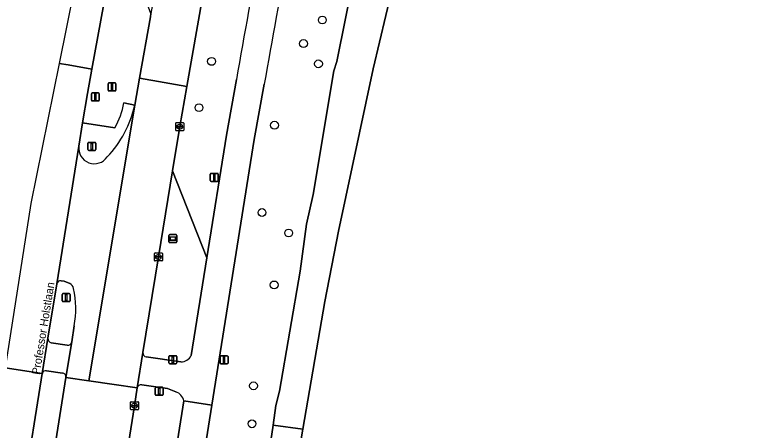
# Model space of a CAD drawing. Extents: x 160203 to 161530, y 379528 to 381797.
# Drawn here: x 160355.6 to 160448.4, y 380603.3 to 380655.1 of the extents above; entities that cross this region are included whole.
import ezdxf

# ---------------------------------------------------------------- set-up
doc = ezdxf.new("R2010")
doc.units = 0
for name, color, linetype in [('IMGEO_Berm_groen', 7, 'Continuous'), ('IMGEO_Boom', 7, 'Continuous'), ('IMGEO_Drukknoppaal', 7, 'Continuous'), ('IMGEO_Fietspad_gesloten', 7, 'Continuous'), ('IMGEO_Fietspad_open', 7, 'Continuous'), ('IMGEO_Grasland_agrarisch', 7, 'Continuous'), ('IMGEO_Kolk', 7, 'Continuous'), ('IMGEO_Lichtmast', 7, 'Continuous'), ('IMGEO_Oever', 7, 'Continuous'), ('IMGEO_Openbare_ruimte_label', 7, 'Continuous'), ('IMGEO_Rijbaan_regionaal_gesloten', 7, 'Continuous'), ('IMGEO_Verkeersbordpaal', 7, 'Continuous'), ('IMGEO_Verkeerseiland_open', 7, 'Continuous'), ('IMGEO_Waterloop', 7, 'Continuous'), ('IMGEO_Wegwijzer', 7, 'Continuous')]:
    doc.layers.add(name, color=color, linetype=linetype)

msp = doc.modelspace()

# ---------------------------------------------------------------- linework, layer by layer
at = {"layer": 'IMGEO_Berm_groen'}
for points in [[(160400.668, 380735.378), (160401.67, 380738.517), (160393.665, 380729.151), (160393.718, 380725.652), (160393.414, 380724.394), (160392.616, 380724.543), (160388.081, 380703.507), (160383.995, 380683.446), (160379.783, 380661.35), (160377.1, 380646.154), (160376.217, 380641.153), (160375.315, 380635.633), (160379.602, 380624.787), (160382.053, 380640.078), (160383.286, 380647.043)], [(160386.211, 380592.747), (160387.862, 380603.942), (160388.223, 380606.389), (160388.675, 380608.166), (160391.266, 380623.144), (160392.046, 380629.012), (160392.89, 380632.678), (160395.463, 380648.127), (160395.831, 380649.266), (160397.982, 380660.047), (160413.118, 380722.694), (160414.318, 380728.603)], [(160372.548, 380654.869), (160372.618, 380655.25), (160368.532, 380666.24), (160365.264, 380648.34), (160364.706, 380645.285), (160364.09, 380641.636), (160368.101, 380641.026)], [(160369.244, 380644.107), (160370.61, 380643.846), (160371.203, 380647.217), (160372.548, 380654.869)], [(160386.76, 380646.455), (160385.522, 380639.561), (160380.205, 380606.406), (160371.189, 380549.526)], [(160379.602, 380624.787), (160375.315, 380635.633), (160373.561, 380624.901), (160371.602, 380612.968)], [(160377.651, 380612.613), (160379.602, 380624.787)], [(160372.039, 380612.43), (160376.36, 380611.804)], [(160359.064, 380610.365), (160356.772, 380595.979), (160358.163, 380585.647), (160362.001, 380609.884)], [(160361.581, 380610.416), (160359.604, 380610.72)], [(160370.92, 380608.573), (160370.572, 380606.348), (160367.595, 380587.549), (160367.388, 380586.261), (160374.855, 380595.163), (160376.723, 380606.946)], [(160375.736, 380608.096), (160374.693, 380608.486), (160371.472, 380608.969)]]:
    msp.add_lwpolyline(points, dxfattribs=at)
for centre, radius, start, end in [((161737.825, 380406.88), 1375.665, 168.507493, 169.945799), ((162016.34, 380355.518), 1655.347, 168.699277, 169.877338), ((160361.073, 380645.386), 8.271, 328.18726, 351.1047), ((160372.143, 380612.961), 0.541, 179.27552, 258.89616), ((160376.321, 380613.301), 1.497, 271.49548, 332.65082), ((160359.517, 380610.264), 0.464, 79.16832, 167.47411), ((160361.54, 380609.952), 0.466, 351.66885, 84.91148), ((160371.397, 380608.49), 0.484, 81.13593, 170.17472), ((160375.175, 380606.616), 1.582, 12.026, 69.2504)]:
    msp.add_arc(centre, radius, start, end, dxfattribs=at)
at = {"layer": 'IMGEO_Boom'}
for centre in [(160394.025, 380654.451), (160391.671, 380651.517), (160380.192, 380649.292), (160393.535, 380648.988), (160378.626, 380643.518), (160388.05, 380641.33), (160386.493, 380630.443), (160389.817, 380627.893), (160388.006, 380621.413), (160385.426, 380608.831), (160385.234, 380604.095)]:
    msp.add_circle(centre, 0.489, dxfattribs=at)
at = {"layer": 'IMGEO_Drukknoppaal'}
for p, q in [((160365.182, 380644.461), (160365.182, 380645.261)), ((160365.182, 380645.261), (160365.182, 380644.461)), ((160365.282, 380645.361), (160366.072, 380645.361)), ((160366.072, 380645.361), (160365.282, 380645.361)), ((160366.172, 380645.261), (160366.172, 380644.461)), ((160366.172, 380644.461), (160366.172, 380645.261)), ((160366.072, 380644.361), (160365.282, 380644.361)), ((160365.282, 380644.361), (160366.072, 380644.361)), ((160364.857, 380639.19), (160365.647, 380639.19)), ((160365.647, 380639.19), (160364.857, 380639.19)), ((160364.757, 380638.29), (160364.757, 380639.09)), ((160364.757, 380639.09), (160364.757, 380638.29)), ((160365.647, 380638.19), (160364.857, 380638.19)), ((160364.857, 380638.19), (160365.647, 380638.19)), ((160365.747, 380639.09), (160365.747, 380638.29)), ((160365.747, 380638.29), (160365.747, 380639.09)), ((160374.861, 380611.685), (160374.861, 380612.485)), ((160374.861, 380612.485), (160374.861, 380611.685)), ((160374.961, 380612.585), (160375.751, 380612.585)), ((160375.751, 380612.585), (160374.961, 380612.585)), ((160375.851, 380612.485), (160375.851, 380611.685)), ((160375.851, 380611.685), (160375.851, 380612.485)), ((160375.751, 380611.585), (160374.961, 380611.585)), ((160374.961, 380611.585), (160375.751, 380611.585))]:
    msp.add_line(p, q, dxfattribs=at)
for points in [[(160365.602, 380645.236), (160365.752, 380645.236), (160365.752, 380644.486), (160365.602, 380644.486), (160365.602, 380645.236)], [(160365.177, 380639.065), (160365.327, 380639.065), (160365.327, 380638.315), (160365.177, 380638.315), (160365.177, 380639.065)], [(160375.281, 380612.46), (160375.431, 380612.46), (160375.431, 380611.71), (160375.281, 380611.71), (160375.281, 380612.46)]]:
    msp.add_lwpolyline(points, dxfattribs=at)
for centre, start, end in [((160365.282, 380645.261), 90, 180), ((160365.282, 380645.261), 90, 180), ((160366.072, 380645.261), 0, 90), ((160366.072, 380645.261), 360, 90), ((160365.282, 380644.461), 180, 270), ((160365.282, 380644.461), 180, 270), ((160366.072, 380644.461), 270, 0), ((160366.072, 380644.461), 270, 0), ((160364.857, 380639.09), 90, 180), ((160364.857, 380639.09), 90, 180), ((160365.647, 380639.09), 0, 90), ((160365.647, 380639.09), 360, 90), ((160364.857, 380638.29), 180, 270), ((160364.857, 380638.29), 180, 270), ((160365.647, 380638.29), 270, 0), ((160365.647, 380638.29), 270, 0), ((160374.961, 380612.485), 90, 180), ((160374.961, 380612.485), 90, 180), ((160375.751, 380612.485), 0, 90), ((160375.751, 380612.485), 360, 90), ((160374.961, 380611.685), 180, 270), ((160374.961, 380611.685), 180, 270), ((160375.751, 380611.685), 270, 0), ((160375.751, 380611.685), 270, 0)]:
    msp.add_arc(centre, 0.1, start, end, dxfattribs=at)
at = {"layer": 'IMGEO_Fietspad_gesloten'}
for points in [[(160383.286, 380647.043), (160382.053, 380640.078), (160379.602, 380624.787), (160377.651, 380612.613)], [(160376.723, 380606.946), (160380.205, 380606.406), (160385.522, 380639.561), (160386.76, 380646.455)], [(160371.602, 380612.968), (160370.92, 380608.573)], [(160376.36, 380611.804), (160372.039, 380612.43)], [(160371.472, 380608.969), (160374.693, 380608.486), (160375.736, 380608.096)]]:
    msp.add_lwpolyline(points, dxfattribs=at)
msp.add_lwpolyline([(160380.205, 380606.406), (160376.723, 380606.946), (160374.855, 380595.163), (160367.706, 380550.056), (160363.967, 380526.659), (160359.706, 380500), (160358.293, 380491.158), (160351.85, 380450.983), (160355.339, 380450.611), (160361.784, 380490.887), (160363.246, 380500), (160367.433, 380526.109), (160371.189, 380549.526)], close=True, dxfattribs=at)
for centre, radius, start, end in [((161737.825, 380406.88), 1375.665, 168.507493, 169.945799), ((162016.34, 380355.518), 1655.347, 168.699277, 169.877338), ((160372.143, 380612.961), 0.541, 179.27552, 258.89616), ((160376.321, 380613.301), 1.497, 271.49548, 332.65082), ((160371.397, 380608.49), 0.484, 81.13593, 170.17472), ((160375.175, 380606.616), 1.582, 12.026, 69.2504)]:
    msp.add_arc(centre, radius, start, end, dxfattribs=at)
at = {"layer": 'IMGEO_Fietspad_open'}
for points in [[(160359.767, 380614.757), (160359.064, 380610.365)], [(160362.159, 380613.9), (160360.16, 380614.208)], [(160362.001, 380609.884), (160362.736, 380614.304)], [(160359.604, 380610.72), (160361.581, 380610.416)]]:
    msp.add_lwpolyline(points, dxfattribs=at)
for centre, radius, start, end in [((160360.28, 380614.709), 0.515, 174.62319, 256.57055), ((160362.219, 380614.429), 0.532, 263.57434, 346.42303), ((160359.517, 380610.264), 0.464, 79.16832, 167.47411), ((160361.54, 380609.952), 0.466, 351.66885, 84.91148)]:
    msp.add_arc(centre, radius, start, end, dxfattribs=at)
at = {"layer": 'IMGEO_Grasland_agrarisch'}
msp.add_lwpolyline([(160502.576, 380648.6), (160500, 380662.54), (160490.099, 380716.119), (160490.004, 380717.605), (160489.849, 380720.043), (160487.28, 380732.369), (160483.606, 380750), (160481.082, 380763.132), (160480.966, 380763.072), (160477.636, 380759.084), (160472.153, 380755.572), (160467.543, 380753.714), (160457.317, 380750.88), (160446.558, 380749.443), (160436.701, 380749.566), (160431.609, 380749.895), (160424.751, 380748.622), (160421.704, 380738.223), (160400.367, 380648.355), (160396.021, 380628.131), (160394.312, 380619.353), (160391.591, 380603.409), (160387.523, 380579.574)], dxfattribs=at)
at = {"layer": 'IMGEO_Kolk'}
for p, q in [((160375.717, 380640.726), (160375.717, 380641.578)), ((160375.792, 380641.652), (160376.644, 380641.652)), ((160375.976, 380641.146), (160375.976, 380641.158)), ((160376.414, 380641.109), (160376.016, 380641.109)), ((160376.019, 380641.195), (160376.417, 380641.195)), ((160376.205, 380641.432), (160376.23, 380641.432)), ((160376.46, 380641.158), (160376.46, 380641.146)), ((160376.718, 380641.578), (160376.718, 380640.726)), ((160376.644, 380640.652), (160375.792, 380640.652)), ((160376.228, 380640.872), (160376.203, 380640.872)), ((160373.059, 380624.476), (160373.059, 380625.328)), ((160373.134, 380625.402), (160373.986, 380625.402)), ((160373.547, 380625.182), (160373.572, 380625.182)), ((160374.06, 380625.328), (160374.06, 380624.476)), ((160373.986, 380624.402), (160373.134, 380624.402)), ((160373.318, 380624.896), (160373.318, 380624.908)), ((160373.756, 380624.859), (160373.358, 380624.859)), ((160373.361, 380624.945), (160373.759, 380624.945)), ((160373.57, 380624.622), (160373.545, 380624.622)), ((160373.802, 380624.908), (160373.802, 380624.896)), ((160370.072, 380605.922), (160370.072, 380606.774)), ((160370.147, 380606.848), (160370.999, 380606.848)), ((160370.56, 380606.628), (160370.585, 380606.628)), ((160371.073, 380606.774), (160371.073, 380605.922)), ((160370.999, 380605.848), (160370.147, 380605.848)), ((160370.331, 380606.342), (160370.331, 380606.354)), ((160370.769, 380606.305), (160370.371, 380606.305)), ((160370.374, 380606.391), (160370.772, 380606.391)), ((160370.583, 380606.068), (160370.558, 380606.068)), ((160370.815, 380606.354), (160370.815, 380606.342))]:
    msp.add_line(p, q, dxfattribs=at)
for points in [[(160375.717, 380640.726), (160375.717, 380641.578)], [(160375.792, 380641.652), (160376.644, 380641.652)], [(160376.718, 380641.578), (160376.718, 380640.726)], [(160376.644, 380640.652), (160375.792, 380640.652)], [(160373.059, 380624.476), (160373.059, 380625.328)], [(160373.134, 380625.402), (160373.986, 380625.402)], [(160374.06, 380625.328), (160374.06, 380624.476)], [(160373.986, 380624.402), (160373.134, 380624.402)], [(160370.072, 380605.922), (160370.072, 380606.774)], [(160370.147, 380606.848), (160370.999, 380606.848)], [(160371.073, 380606.774), (160371.073, 380605.922)], [(160370.999, 380605.848), (160370.147, 380605.848)]]:
    msp.add_lwpolyline(points, dxfattribs=at)
for centre, radius, start, end in [((160375.794, 380641.576), 0.0765, 91.55205, 178.44795), ((160375.794, 380641.576), 0.0765, 91.55205, 178.44795), ((160376.016, 380641.155), 0.0403, 85.87752, 175.75265), ((160376.013, 380641.145), 0.0366, 178.93798, 274.71019), ((160376.417, 380641.152), 0.043, 264.86636, 352.45326), ((160376.421, 380641.157), 0.0386, 1.73085, 96.63898), ((160376.642, 380641.576), 0.0765, 1.55205, 88.44795), ((160376.642, 380641.576), 0.0765, 1.55205, 88.44795), ((160375.794, 380640.728), 0.0765, 181.55205, 268.44795), ((160375.794, 380640.728), 0.0765, 181.55205, 268.44795), ((160376.642, 380640.728), 0.0765, 271.55205, 358.44795), ((160376.642, 380640.728), 0.0765, 271.55205, 358.44795), ((160373.136, 380625.326), 0.0765, 91.55205, 178.44795), ((160373.136, 380625.326), 0.0765, 91.55205, 178.44795), ((160373.984, 380625.326), 0.0765, 1.55205, 88.44795), ((160373.984, 380625.326), 0.0765, 1.55205, 88.44795), ((160373.136, 380624.478), 0.0765, 181.55205, 268.44795), ((160373.136, 380624.478), 0.0765, 181.55205, 268.44795), ((160373.358, 380624.905), 0.0403, 85.87752, 175.75265), ((160373.355, 380624.895), 0.0366, 178.93798, 274.71019), ((160373.759, 380624.902), 0.043, 264.86636, 352.45326), ((160373.763, 380624.907), 0.0386, 1.73085, 96.63898), ((160373.984, 380624.478), 0.0765, 271.55205, 358.44795), ((160373.984, 380624.478), 0.0765, 271.55205, 358.44795), ((160370.149, 380606.772), 0.0765, 91.55205, 178.44795), ((160370.149, 380606.772), 0.0765, 91.55205, 178.44795), ((160370.997, 380606.772), 0.0765, 1.55205, 88.44795), ((160370.997, 380606.772), 0.0765, 1.55205, 88.44795), ((160370.149, 380605.924), 0.0765, 181.55205, 268.44795), ((160370.149, 380605.924), 0.0765, 181.55205, 268.44795), ((160370.371, 380606.351), 0.0403, 85.87752, 175.75265), ((160370.368, 380606.341), 0.0366, 178.93798, 274.71019), ((160370.772, 380606.348), 0.043, 264.86636, 352.45326), ((160370.776, 380606.353), 0.0386, 1.73085, 96.63898), ((160370.997, 380605.924), 0.0765, 271.55205, 358.44795), ((160370.997, 380605.924), 0.0765, 271.55205, 358.44795)]:
    msp.add_arc(centre, radius, start, end, dxfattribs=at)
for centre, major_axis, ratio, start_param, end_param in [((160376.204, 380641.152), (-0.387, 0.002), 0.722429, 4.712389, 7.853982), ((160376.229, 380641.152), (-0.39, 0.002), 0.717154, 1.570796, 4.712389), ((160373.546, 380624.902), (-0.387, 0.002), 0.722429, 4.712389, 7.853982), ((160373.571, 380624.902), (-0.39, 0.002), 0.717154, 1.570796, 4.712389), ((160370.559, 380606.348), (-0.387, 0.002), 0.722429, 4.712389, 7.853982), ((160370.584, 380606.348), (-0.39, 0.002), 0.717154, 1.570796, 4.712389)]:
    msp.add_ellipse(centre, major_axis=major_axis, ratio=ratio, start_param=start_param, end_param=end_param, dxfattribs=at)
at = {"layer": 'IMGEO_Lichtmast'}
for p, q in [((160367.366, 380646.605), (160368.156, 380646.605)), ((160368.156, 380646.605), (160367.366, 380646.605)), ((160367.266, 380645.705), (160367.266, 380646.505)), ((160367.266, 380646.505), (160367.266, 380645.705)), ((160368.156, 380645.605), (160367.366, 380645.605)), ((160367.366, 380645.605), (160368.156, 380645.605)), ((160368.256, 380646.505), (160368.256, 380645.705)), ((160368.256, 380645.705), (160368.256, 380646.505)), ((160380.036, 380634.421), (160380.036, 380635.221)), ((160380.036, 380635.221), (160380.036, 380634.421)), ((160380.136, 380635.321), (160380.926, 380635.321)), ((160380.926, 380635.321), (160380.136, 380635.321)), ((160381.026, 380635.221), (160381.026, 380634.421)), ((160381.026, 380634.421), (160381.026, 380635.221)), ((160380.926, 380634.321), (160380.136, 380634.321)), ((160380.136, 380634.321), (160380.926, 380634.321)), ((160361.542, 380619.432), (160361.542, 380620.232)), ((160361.542, 380620.232), (160361.542, 380619.432)), ((160361.642, 380620.332), (160362.432, 380620.332)), ((160362.432, 380620.332), (160361.642, 380620.332)), ((160362.532, 380620.232), (160362.532, 380619.432)), ((160362.532, 380619.432), (160362.532, 380620.232)), ((160362.432, 380619.332), (160361.642, 380619.332)), ((160361.642, 380619.332), (160362.432, 380619.332)), ((160381.254, 380611.675), (160381.254, 380612.475)), ((160381.254, 380612.475), (160381.254, 380611.675)), ((160381.354, 380612.575), (160382.144, 380612.575)), ((160382.144, 380612.575), (160381.354, 380612.575)), ((160382.244, 380612.475), (160382.244, 380611.675)), ((160382.244, 380611.675), (160382.244, 380612.475)), ((160382.144, 380611.575), (160381.354, 380611.575)), ((160381.354, 380611.575), (160382.144, 380611.575))]:
    msp.add_line(p, q, dxfattribs=at)
for points in [[(160367.686, 380646.48), (160367.836, 380646.48), (160367.836, 380645.73), (160367.686, 380645.73), (160367.686, 380646.48)], [(160380.456, 380635.196), (160380.606, 380635.196), (160380.606, 380634.446), (160380.456, 380634.446), (160380.456, 380635.196)], [(160361.962, 380620.207), (160362.112, 380620.207), (160362.112, 380619.457), (160361.962, 380619.457), (160361.962, 380620.207)], [(160381.674, 380612.45), (160381.824, 380612.45), (160381.824, 380611.7), (160381.674, 380611.7), (160381.674, 380612.45)]]:
    msp.add_lwpolyline(points, dxfattribs=at)
for centre, start, end in [((160367.366, 380646.505), 90, 180), ((160367.366, 380646.505), 90, 180), ((160368.156, 380646.505), 0, 90), ((160368.156, 380646.505), 360, 90), ((160367.366, 380645.705), 180, 270), ((160367.366, 380645.705), 180, 270), ((160368.156, 380645.705), 270, 0), ((160368.156, 380645.705), 270, 0), ((160380.136, 380635.221), 90, 180), ((160380.136, 380635.221), 90, 180), ((160380.926, 380635.221), 0, 90), ((160380.926, 380635.221), 360, 90), ((160380.136, 380634.421), 180, 270), ((160380.136, 380634.421), 180, 270), ((160380.926, 380634.421), 270, 0), ((160380.926, 380634.421), 270, 0), ((160361.642, 380620.232), 90, 180), ((160361.642, 380620.232), 90, 180), ((160362.432, 380620.232), 0, 90), ((160362.432, 380620.232), 360, 90), ((160361.642, 380619.432), 180, 270), ((160361.642, 380619.432), 180, 270), ((160362.432, 380619.432), 270, 0), ((160362.432, 380619.432), 270, 0), ((160381.354, 380612.475), 90, 180), ((160381.354, 380612.475), 90, 180), ((160382.144, 380612.475), 0, 90), ((160382.144, 380612.475), 360, 90), ((160381.354, 380611.675), 180, 270), ((160381.354, 380611.675), 180, 270), ((160382.144, 380611.675), 270, 0), ((160382.144, 380611.675), 270, 0)]:
    msp.add_arc(centre, 0.1, start, end, dxfattribs=at)
at = {"layer": 'IMGEO_Oever'}
msp.add_lwpolyline([(160387.523, 380579.574), (160391.591, 380603.409), (160387.862, 380603.942), (160386.211, 380592.747)], dxfattribs=at)
at = {"layer": 'IMGEO_Rijbaan_regionaal_gesloten'}
for points in [[(160361.179, 380649.047), (160362.287, 380648.845), (160365.264, 380648.34), (160368.532, 380666.24), (160375.036, 380700.809), (160376.868, 380709.594), (160379.775, 380722.42), (160381.017, 380727.317), (160382.072, 380731.991), (160378.155, 380732.936), (160377.905, 380731.881)], [(160379.783, 380661.35), (160383.995, 380683.446), (160388.081, 380703.507), (160392.616, 380724.543), (160393.665, 380729.151), (160387.265, 380730.705), (160386.475, 380726.144), (160385.305, 380719.752), (160381.038, 380699.156), (160376.956, 380678.451), (160372.618, 380655.25), (160372.548, 380654.869), (160371.203, 380647.217), (160374.274, 380646.656), (160377.1, 380646.154)], [(160354.423, 380611.084), (160359.064, 380610.365), (160359.767, 380614.757), (160360.869, 380621.546), (160363.619, 380638.713), (160364.09, 380641.636), (160364.706, 380645.285), (160365.264, 380648.34), (160362.287, 380648.845), (160361.179, 380649.047), (160357.648, 380631.559)], [(160375.315, 380635.633), (160376.217, 380641.153), (160377.1, 380646.154), (160374.274, 380646.656), (160371.203, 380647.217), (160370.61, 380643.846), (160364.88, 380609.461), (160368.048, 380608.995), (160370.92, 380608.573), (160371.602, 380612.968), (160373.561, 380624.901)], [(160307.532, 380313.4), (160308.269, 380313.283), (160311.667, 380312.745), (160315.52, 380337.005), (160317.914, 380352.077), (160328.155, 380416.671), (160330.069, 380428.623), (160330.26, 380429.737), (160341.49, 380500), (160346.119, 380528.965), (160346.201, 380529.483), (160352.778, 380570.911), (160356.772, 380595.979), (160359.064, 380610.365), (160354.423, 380611.084)]]:
    msp.add_lwpolyline(points, close=True, dxfattribs=at)
for points in [[(160363.04, 380616.293), (160362.736, 380614.304), (160362.001, 380609.884), (160364.88, 380609.461), (160370.61, 380643.846)], [(160363.619, 380638.713), (160360.869, 380621.546)], [(160361.396, 380621.916), (160361.81, 380621.874), (160362.509, 380621.585)], [(160361.773, 380551.056), (160364.666, 380569.299), (160367.388, 380586.261), (160367.595, 380587.549), (160370.572, 380606.348), (160370.92, 380608.573), (160368.048, 380608.995), (160364.88, 380609.461), (160362.001, 380609.884), (160358.163, 380585.647), (160355.748, 380570.396), (160349.14, 380529.016)]]:
    msp.add_lwpolyline(points, dxfattribs=at)
for centre, radius, start, end in [((160357.193, 380646.845), 13.748, 316.47815, 347.39894), ((160365.557, 380638.487), 1.951, 173.35829, 325.34896), ((160361.333, 380621.446), 0.474, 82.33913, 167.80528), ((160362.128, 380620.854), 0.825, 7.90279, 62.50328), ((160352.516, 380618.417), 10.736, 348.58919, 13.73959)]:
    msp.add_arc(centre, radius, start, end, dxfattribs=at)
at = {"layer": 'IMGEO_Verkeersbordpaal'}
for p, q in [((160373.156, 380607.75), (160373.156, 380608.55)), ((160373.156, 380608.55), (160373.156, 380607.75)), ((160373.256, 380608.65), (160374.046, 380608.65)), ((160374.046, 380608.65), (160373.256, 380608.65)), ((160374.146, 380608.55), (160374.146, 380607.75)), ((160374.146, 380607.75), (160374.146, 380608.55)), ((160374.046, 380607.65), (160373.256, 380607.65)), ((160373.256, 380607.65), (160374.046, 380607.65))]:
    msp.add_line(p, q, dxfattribs=at)
msp.add_lwpolyline([(160373.576, 380608.525), (160373.726, 380608.525), (160373.726, 380607.775), (160373.576, 380607.775), (160373.576, 380608.525)], dxfattribs=at)
for centre, start, end in [((160373.256, 380608.55), 90, 180), ((160373.256, 380608.55), 90, 180), ((160374.046, 380608.55), 0, 90), ((160374.046, 380608.55), 360, 90), ((160373.256, 380607.75), 180, 270), ((160373.256, 380607.75), 180, 270), ((160374.046, 380607.75), 270, 0), ((160374.046, 380607.75), 270, 0)]:
    msp.add_arc(centre, 0.1, start, end, dxfattribs=at)
at = {"layer": 'IMGEO_Verkeerseiland_open'}
for points in [[(160370.61, 380643.846), (160369.244, 380644.107)], [(160368.101, 380641.026), (160364.09, 380641.636), (160363.619, 380638.713)], [(160360.869, 380621.546), (160359.767, 380614.757)], [(160362.509, 380621.585), (160361.81, 380621.874), (160361.396, 380621.916)], [(160362.736, 380614.304), (160363.04, 380616.293)], [(160360.16, 380614.208), (160362.159, 380613.9)]]:
    msp.add_lwpolyline(points, dxfattribs=at)
for centre, radius, start, end in [((160357.193, 380646.845), 13.748, 316.47815, 347.39894), ((160361.073, 380645.386), 8.271, 328.18726, 351.1047), ((160365.557, 380638.487), 1.951, 173.35829, 325.34896), ((160361.333, 380621.446), 0.474, 82.33913, 167.80528), ((160362.128, 380620.854), 0.825, 7.90279, 62.50328), ((160352.516, 380618.417), 10.736, 348.58919, 13.73959), ((160360.28, 380614.709), 0.515, 174.62319, 256.57055), ((160362.219, 380614.429), 0.532, 263.57434, 346.42303)]:
    msp.add_arc(centre, radius, start, end, dxfattribs=at)
at = {"layer": 'IMGEO_Waterloop'}
msp.add_lwpolyline([(160414.318, 380728.603), (160413.118, 380722.694), (160397.982, 380660.047), (160395.831, 380649.266), (160395.463, 380648.127), (160392.89, 380632.678), (160392.046, 380629.012), (160391.266, 380623.144), (160388.675, 380608.166), (160388.223, 380606.389), (160387.862, 380603.942), (160391.591, 380603.409), (160394.312, 380619.353), (160396.021, 380628.131), (160400.367, 380648.355), (160421.704, 380738.223)], dxfattribs=at)
at = {"layer": 'IMGEO_Wegwijzer'}
for p, q in [((160374.869, 380626.796), (160374.869, 380627.596)), ((160374.869, 380627.596), (160374.869, 380626.796)), ((160374.969, 380627.696), (160375.759, 380627.696)), ((160375.759, 380627.696), (160374.969, 380627.696)), ((160375.859, 380627.596), (160375.859, 380626.796)), ((160375.859, 380626.796), (160375.859, 380627.596)), ((160375.759, 380626.696), (160374.969, 380626.696)), ((160374.969, 380626.696), (160375.759, 380626.696))]:
    msp.add_line(p, q, dxfattribs=at)
for points in [[(160374.97, 380627.428), (160375.758, 380627.428), (160375.758, 380626.964), (160374.97, 380626.964), (160374.97, 380627.428)], [(160375.035, 380627.363), (160375.035, 380627.029), (160375.693, 380627.029), (160375.693, 380627.363), (160375.035, 380627.363)]]:
    msp.add_lwpolyline(points, dxfattribs=at)
for centre, start, end in [((160374.969, 380627.596), 90, 180), ((160374.969, 380627.596), 90, 180), ((160375.759, 380627.596), 0, 90), ((160375.759, 380627.596), 360, 90), ((160374.969, 380626.796), 180, 270), ((160374.969, 380626.796), 180, 270), ((160375.759, 380626.796), 270, 0), ((160375.759, 380626.796), 270, 0)]:
    msp.add_arc(centre, 0.1, start, end, dxfattribs=at)

# ---------------------------------------------------------------- texts
at = {"layer": 'IMGEO_Openbare_ruimte_label'}
msp.add_text('Professor Holstlaan', height=1, rotation=80.73548, dxfattribs=at).set_placement((160358.721, 380610.158))

doc.saveas('drawing.dxf')
